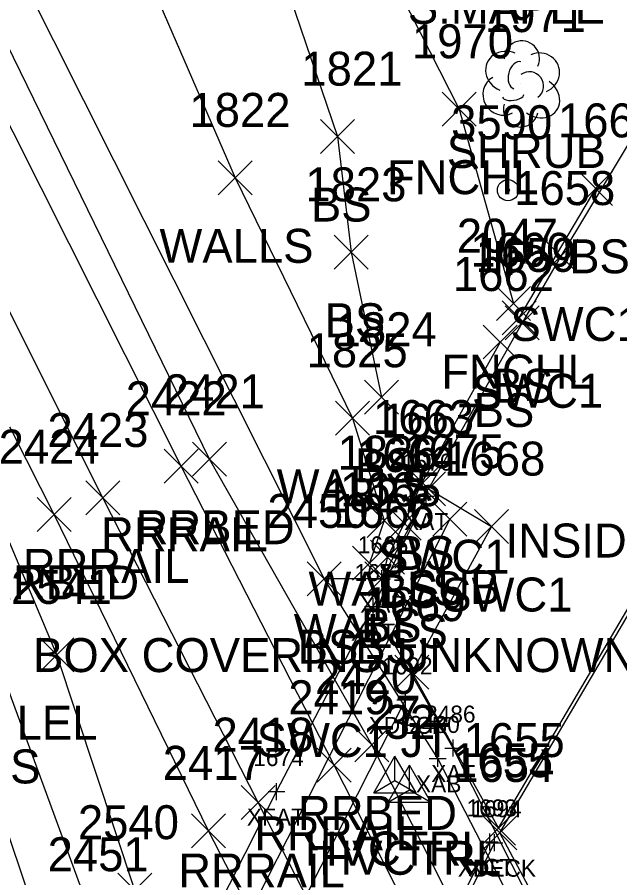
# Model space of a CAD drawing. Extents: x 1462668 to 1465147, y 550359 to 557351.
# Drawn here: x 1464652.7 to 1464688.2, y 552680.5 to 552731.2 of the extents above; entities that cross this region are included whole.
import ezdxf

# ---------------------------------------------------------------- set-up
doc = ezdxf.new("R2010")
doc.units = 0
for name, color, linetype in [('B_A', 7, 'Continuous'), ('B_I', 7, 'Continuous'), ('B_TIC', 7, 'Continuous'), ('BDC', 7, 'Continuous'), ('BELB', 7, 'Continuous'), ('BF', 7, 'Continuous'), ('BSUBM', 7, 'Continuous'), ('C_A', 7, 'Continuous'), ('C_I', 7, 'Continuous'), ('CPSM', 7, 'Continuous'), ('D_C', 7, 'Continuous'), ('L_A', 7, 'Continuous'), ('L_C', 7, 'Continuous'), ('L_I', 7, 'Continuous'), ('L_TIC', 7, 'Continuous'), ('LARO', 7, 'Continuous'), ('LELB', 7, 'Continuous'), ('LFNC', 7, 'Continuous'), ('LSH', 7, 'Continuous'), ('LWS', 7, 'Continuous'), ('M_A', 7, 'Continuous'), ('M_I', 7, 'Continuous'), ('MPIR', 7, 'Continuous'), ('P_I', 7, 'Continuous'), ('P_TIC', 7, 'Continuous'), ('PSP', 7, 'Continuous'), ('R_A', 7, 'Continuous'), ('R_I', 7, 'Continuous'), ('R_TIC', 7, 'Continuous'), ('RC', 7, 'Continuous'), ('RR', 7, 'Continuous'), ('RRB', 7, 'Continuous'), ('RSW', 7, 'Continuous'), ('U_A', 7, 'Continuous'), ('U_C', 7, 'Continuous'), ('U_I', 7, 'Continuous'), ('U_TIC', 7, 'Continuous'), ('UUU', 7, 'Continuous')]:
    doc.layers.add(name, color=color, linetype=linetype)

msp = doc.modelspace()

# ---------------------------------------------------------------- linework, layer by layer
at = {"layer": 'B_TIC'}
for p, q in [((1464676.76, 552702.981), (1464676.836, 552702.981)), ((1464674.159, 552698.116), (1464674.235, 552698.116)), ((1464673.643, 552696.482), (1464673.718, 552696.482)), ((1464675.542, 552690.989), (1464675.618, 552690.989)), ((1464678.359, 552688.151), (1464678.434, 552688.151)), ((1464677.446, 552687.542), (1464677.522, 552687.542)), ((1464667.956, 552685.592), (1464668.032, 552685.592)), ((1464680.517, 552682.631), (1464680.592, 552682.631)), ((1464680.788, 552682.58), (1464680.864, 552682.58))]:
    msp.add_line(p, q, dxfattribs=at)
for points in [[(1464676.757, 552702.481), (1464676.757, 552703.481)], [(1464676.257, 552702.981), (1464677.257, 552702.981)], [(1464674.156, 552697.616), (1464674.156, 552698.616)], [(1464673.656, 552698.116), (1464674.656, 552698.116)], [(1464673.639, 552695.982), (1464673.639, 552696.982)], [(1464673.139, 552696.482), (1464674.139, 552696.482)], [(1464675.539, 552690.489), (1464675.539, 552691.489)], [(1464675.039, 552690.989), (1464676.039, 552690.989)], [(1464678.355, 552687.651), (1464678.355, 552688.651)], [(1464677.443, 552687.042), (1464677.443, 552688.042)], [(1464677.855, 552688.151), (1464678.855, 552688.151)], [(1464676.943, 552687.542), (1464677.943, 552687.542)], [(1464667.953, 552685.092), (1464667.953, 552686.092)], [(1464667.453, 552685.592), (1464668.453, 552685.592)], [(1464680.513, 552682.131), (1464680.513, 552683.131)], [(1464680.785, 552682.08), (1464680.785, 552683.08)], [(1464680.013, 552682.631), (1464681.013, 552682.631)], [(1464680.285, 552682.58), (1464681.285, 552682.58)]]:
    msp.add_lwpolyline(points, dxfattribs=at)
at = {"layer": 'BDC'}
msp.add_lwpolyline([(1464680.513, 552682.631), (1464669.667, 552661.383), (1464666.469, 552656.596)], dxfattribs=at)
at = {"layer": 'BELB'}
for points in [[(1464662.218, 552664.718), (1464666.341, 552672.848), (1464675.539, 552690.989)], [(1464680.785, 552682.58), (1464669.962, 552661.215), (1464666.703, 552656.487)]]:
    msp.add_lwpolyline(points, dxfattribs=at)
at = {"layer": 'BF'}
for points in [[(1464667.953, 552685.592), (1464673.639, 552696.482)], [(1464659.334, 552668.851), (1464662.413, 552674.652), (1464667.953, 552685.592)]]:
    msp.add_lwpolyline(points, dxfattribs=at)
at = {"layer": 'BSUBM'}
for points in [[(1464676.757, 552702.981), (1464673.639, 552696.482)], [(1464674.156, 552698.116), (1464676.757, 552702.981)], [(1464674.156, 552698.116), (1464670.761, 552698.112)], [(1464677.443, 552687.542), (1464670.761, 552698.112)], [(1464678.355, 552688.151), (1464673.639, 552696.482)], [(1464723.043, 552601.401), (1464713.026, 552620.249), (1464708.313, 552629.74), (1464700.555, 552644.714), (1464687.566, 552669.892), (1464678.355, 552688.151)], [(1464722.837, 552599.912), (1464712.418, 552619.848), (1464699.886, 552644.257), (1464686.833, 552669.359), (1464677.443, 552687.542)]]:
    msp.add_lwpolyline(points, dxfattribs=at)
at = {"layer": 'CPSM'}
for p, q in [((1464673.678, 552685.516), (1464674.928, 552687.681)), ((1464676.178, 552685.516), (1464674.928, 552687.681)), ((1464674.928, 552686.237), (1464674.928, 552687.681)), ((1464674.536, 552684.973), (1464675.786, 552687.138)), ((1464677.036, 552684.973), (1464675.786, 552687.138)), ((1464675.786, 552685.694), (1464675.786, 552687.138)), ((1464673.678, 552685.516), (1464674.928, 552686.237)), ((1464674.928, 552686.237), (1464674.928, 552686.237)), ((1464674.928, 552686.237), (1464676.178, 552685.516)), ((1464673.678, 552685.516), (1464676.178, 552685.516)), ((1464674.536, 552684.973), (1464675.786, 552685.694)), ((1464675.786, 552685.694), (1464675.786, 552685.694)), ((1464675.786, 552685.694), (1464677.036, 552684.973)), ((1464674.536, 552684.973), (1464677.036, 552684.973))]:
    msp.add_line(p, q, dxfattribs=at)
at = {"layer": 'L_TIC'}
for points in [[(1464677.707, 552724.755), (1464679.707, 552726.755)], [(1464679.707, 552724.755), (1464677.707, 552726.755)], [(1464670.542, 552723.144), (1464672.542, 552725.144)], [(1464672.542, 552723.144), (1464670.542, 552725.144)], [(1464664.52, 552720.715), (1464666.52, 552722.715)], [(1464666.52, 552720.715), (1464664.52, 552722.715)], [(1464685.745, 552720.098), (1464687.745, 552722.098)], [(1464687.745, 552720.098), (1464685.745, 552722.098)], [(1464671.348, 552716.335), (1464673.348, 552718.335)], [(1464673.348, 552716.335), (1464671.348, 552718.335)], [(1464680.909, 552713.313), (1464682.909, 552715.313)], [(1464682.909, 552713.313), (1464680.909, 552715.313)], [(1464681.243, 552712.482), (1464683.243, 552714.482)], [(1464683.243, 552712.482), (1464681.243, 552714.482)], [(1464680.123, 552711.054), (1464682.123, 552713.054)], [(1464682.123, 552711.054), (1464680.123, 552713.054)], [(1464673.131, 552707.802), (1464675.131, 552709.802)], [(1464675.131, 552707.802), (1464673.131, 552709.802)], [(1464671.421, 552706.566), (1464673.421, 552708.566)], [(1464673.421, 552706.566), (1464671.421, 552708.566)], [(1464675.423, 552702.634), (1464677.423, 552704.634)], [(1464677.423, 552702.634), (1464675.423, 552704.634)], [(1464673.293, 552700.543), (1464675.293, 552702.543)], [(1464675.293, 552700.543), (1464673.293, 552702.543)], [(1464674.475, 552700.398), (1464676.475, 552702.398)], [(1464676.475, 552700.398), (1464674.475, 552702.398)], [(1464672.431, 552698.034), (1464674.431, 552700.034)], [(1464674.431, 552698.034), (1464672.431, 552700.034)], [(1464673.486, 552698.383), (1464675.486, 552700.383)], [(1464675.486, 552698.383), (1464673.486, 552700.383)], [(1464669.761, 552697.112), (1464671.761, 552699.112)], [(1464671.761, 552697.112), (1464669.761, 552699.112)], [(1464673.156, 552697.116), (1464675.156, 552699.116)], [(1464675.156, 552697.116), (1464673.156, 552699.116)], [(1464654.013, 552692.639), (1464656.013, 552694.639)], [(1464656.013, 552692.639), (1464654.013, 552694.639)], [(1464658.607, 552678.788), (1464660.607, 552680.788)], [(1464660.607, 552678.788), (1464658.607, 552680.788)]]:
    msp.add_lwpolyline(points, dxfattribs=at)
at = {"layer": 'LARO'}
msp.add_lwpolyline([(1464658.959, 552674.491), (1464659.607, 552679.788), (1464655.013, 552693.639), (1464649.27, 552707.282)], dxfattribs=at)
at = {"layer": 'LELB'}
for points in [[(1464605.992, 552829.954), (1464617.903, 552805.102), (1464635.924, 552775.462), (1464644.18, 552750.936), (1464670.761, 552698.112)], [(1464591.837, 552823.151), (1464604.584, 552798.4), (1464620.531, 552768.212), (1464633.366, 552738.896), (1464646.04, 552708.211), (1464657.171, 552677.902), (1464659.575, 552669.465), (1464660.96, 552669.665)], [(1464666.872, 552737.886), (1464671.542, 552724.144), (1464672.348, 552717.335), (1464674.131, 552708.802)], [(1464682.243, 552713.482), (1464686.745, 552721.098)], [(1464681.123, 552712.054), (1464676.423, 552703.634), (1464675.475, 552701.398), (1464674.486, 552699.383), (1464674.156, 552698.116)]]:
    msp.add_lwpolyline(points, dxfattribs=at)
at = {"layer": 'LFNC'}
msp.add_lwpolyline([(1464622.755, 552840.374), (1464640.528, 552802.915), (1464653.99, 552774.381), (1464678.707, 552725.755), (1464681.909, 552714.313)], dxfattribs=at)
at = {"layer": 'LSH'}
msp.add_line((1464682.348, 552727.298), (1464682.348, 552727.298), dxfattribs=at)
msp.add_line((1464682.348, 552727.298), (1464682.348, 552727.298), dxfattribs=at)
msp.add_arc((1464682.395, 552728.732), 1.047, 335.5272, 180.9563, dxfattribs=at)
for centre, major_axis, ratio, start_param, end_param in [((1464681.556, 552727.965), (1.21, -0.512), 0.895232, 1.570796, 4.712389), ((1464683.39, 552727.882), (-1.141, -0.483), 0.949671, 1.570796, 4.712389), ((1464682.14, 552727.756), (-0.208, -0.792), 0.645439, 3.141593, 6.283185), ((1464682.848, 552727.131), (-0.5, 0.667), 0.989748, 3.141593, 6.283185), ((1464681.265, 552726.589), (0.584, -1.042), 0.959034, 3.141593, 6.283185), ((1464683.348, 552726.465), (-1.09, 0.792), 0.841452, 1.570796, 4.712389), ((1464681.89, 552726.548), (-0.625, -0.083), 0.423636, 0, 3.141593), ((1464682.348, 552725.798), (0.265, 1.061), 0.942809, 1.570796, 4.712389)]:
    msp.add_ellipse(centre, major_axis=major_axis, ratio=ratio, start_param=start_param, end_param=end_param, dxfattribs=at)
at = {"layer": 'LWS'}
for points in [[(1464627.227, 552807.88), (1464624.579, 552807.197), (1464630.268, 552793.197), (1464640.043, 552768.12), (1464646.829, 552754.919), (1464648.101, 552754.433), (1464659.033, 552736.713), (1464665.52, 552721.715), (1464672.421, 552707.566), (1464674.293, 552701.543), (1464673.431, 552699.034)], [(1464628.323, 552737.747), (1464630.463, 552738.737), (1464636.481, 552723.859), (1464640.409, 552715.693), (1464643.848, 552708.405), (1464644.066, 552707.906), (1464644.246, 552705.998), (1464645.171, 552703.317), (1464649.444, 552691.071), (1464655.056, 552674.447), (1464657.686, 552668.432), (1464659.187, 552668.867)]]:
    msp.add_lwpolyline(points, dxfattribs=at)
at = {"layer": 'MPIR'}
for radius in [0.625, 0.0833]:
    msp.add_circle((1464681.583, 552720.991), radius, dxfattribs=at)
at = {"layer": 'P_TIC'}
for points in [[(1464680.101, 552682.158), (1464682.101, 552684.158)], [(1464682.101, 552682.158), (1464680.101, 552684.158)]]:
    msp.add_lwpolyline(points, dxfattribs=at)
at = {"layer": 'PSP'}
msp.add_lwpolyline([(1464713.42, 552621.664), (1464703.882, 552639.321), (1464698.154, 552650.89), (1464690.708, 552665.219), (1464681.101, 552683.158), (1464703.999, 552722.049), (1464716.476, 552737.914), (1464734.78, 552760.749), (1464735.815, 552761.915), (1464745.244, 552772.268), (1464746.275, 552773.345), (1464761.553, 552790.01), (1464762.974, 552792.101), (1464763.764, 552794.246), (1464784.888, 552812.77), (1464795.307, 552821.347), (1464823.73, 552847.994), (1464827.491, 552852.408)], dxfattribs=at)
at = {"layer": 'R_TIC'}
for points in [[(1464683.688, 552716.115), (1464685.688, 552718.115)], [(1464685.688, 552716.115), (1464683.688, 552718.115)], [(1464681.423, 552712.181), (1464683.423, 552714.181)], [(1464683.423, 552712.181), (1464681.423, 552714.181)], [(1464663.014, 552704.151), (1464665.014, 552706.151)], [(1464665.014, 552704.151), (1464663.014, 552706.151)], [(1464661.335, 552703.74), (1464663.335, 552705.74)], [(1464663.335, 552703.74), (1464661.335, 552705.74)], [(1464675.9, 552702.42), (1464677.9, 552704.42)], [(1464677.9, 552702.42), (1464675.9, 552704.42)], [(1464656.727, 552701.874), (1464658.727, 552703.874)], [(1464658.727, 552701.874), (1464656.727, 552703.874)], [(1464653.855, 552700.899), (1464655.855, 552702.899)], [(1464655.855, 552700.899), (1464653.855, 552702.899)], [(1464679.616, 552700.19), (1464681.616, 552702.19)], [(1464681.616, 552700.19), (1464679.616, 552702.19)], [(1464674.923, 552691.623), (1464676.923, 552693.623)], [(1464676.923, 552691.623), (1464674.923, 552693.623)], [(1464672.574, 552687.335), (1464674.574, 552689.335)], [(1464674.574, 552687.335), (1464672.574, 552689.335)], [(1464670.35, 552686.141), (1464672.35, 552688.141)], [(1464672.35, 552686.141), (1464670.35, 552688.141)], [(1464665.878, 552683.945), (1464667.878, 552685.945)], [(1464667.878, 552683.945), (1464665.878, 552685.945)], [(1464680.027, 552682.437), (1464682.027, 552684.437)], [(1464682.027, 552682.437), (1464680.027, 552684.437)], [(1464662.948, 552682.282), (1464664.948, 552684.282)], [(1464664.948, 552682.282), (1464662.948, 552684.282)]]:
    msp.add_lwpolyline(points, dxfattribs=at)
at = {"layer": 'RC'}
msp.add_lwpolyline([(1464681.027, 552683.437), (1464703.888, 552722.216), (1464716.213, 552738.058), (1464734.65, 552760.884), (1464735.67, 552761.965), (1464745.167, 552772.414), (1464746.115, 552773.418), (1464761.316, 552790.158), (1464762.705, 552792.216), (1464763.558, 552794.277), (1464763.469, 552797.082), (1464762.503, 552800.027), (1464761.265, 552802.911), (1464759.396, 552805.483), (1464759.23, 552805.341)], dxfattribs=at)
at = {"layer": 'RR'}
for points in [[(1464849.389, 552249.534), (1464842.819, 552270.793), (1464835.11, 552294.838), (1464826.262, 552322.52), (1464813.909, 552358.251), (1464808.668, 552373.872), (1464804.992, 552384.746), (1464790.19, 552425.007), (1464777.181, 552458.665), (1464762.364, 552494.605), (1464744.909, 552535.145), (1464735.628, 552555.847), (1464721.293, 552586.6), (1464702.021, 552626.346), (1464686.842, 552656.687), (1464671.35, 552687.141), (1464662.335, 552704.74), (1464642.534, 552744.081), (1464629.159, 552771.135), (1464613.477, 552803.16), (1464601.343, 552828.316)], [(1464844.813, 552247.755), (1464838.177, 552269.149), (1464830.386, 552293.617), (1464821.392, 552321.548), (1464809.517, 552356.645), (1464804.149, 552372.473), (1464800.295, 552383.078), (1464785.596, 552423.206), (1464772.719, 552456.472), (1464757.811, 552492.705), (1464740.233, 552533.386), (1464731.218, 552553.662), (1464716.736, 552584.611), (1464697.665, 552624.112), (1464682.453, 552654.497), (1464666.878, 552684.945), (1464657.727, 552702.874), (1464638.134, 552741.98), (1464624.708, 552768.998), (1464609.228, 552800.971), (1464596.703, 552826.136)]]:
    msp.add_lwpolyline(points, dxfattribs=at)
at = {"layer": 'RRB'}
for points in [[(1464851.042, 552250.445), (1464845.147, 552271.635), (1464837.544, 552295.462), (1464828.768, 552323.575), (1464816.78, 552359.11), (1464810.928, 552374.769), (1464807.843, 552386.028), (1464792.774, 552426.038), (1464778.944, 552461.754), (1464771.168, 552477.614), (1464764.619, 552495.611), (1464747.04, 552536.302), (1464737.618, 552557.165), (1464723.44, 552587.94), (1464704.535, 552627.922), (1464689.191, 552657.618), (1464673.574, 552688.335), (1464664.014, 552705.151), (1464644.495, 552745.11), (1464631.556, 552772.375), (1464615.641, 552804.178), (1464603.908, 552829.416)], [(1464842.442, 552246.931), (1464836.486, 552268.553), (1464828.066, 552292.901), (1464819.091, 552320.895), (1464807.286, 552355.87), (1464801.457, 552371.532), (1464797.599, 552381.724), (1464783.012, 552422.471), (1464769.406, 552454.584), (1464755.315, 552491.81), (1464738.611, 552532.376), (1464729.391, 552552.755), (1464715, 552583.837), (1464695.071, 552622.976), (1464679.554, 552652.995), (1464663.948, 552683.282), (1464654.855, 552701.899), (1464635.344, 552740.456), (1464622.383, 552767.72), (1464607.066, 552799.752), (1464594.744, 552825)]]:
    msp.add_lwpolyline(points, dxfattribs=at)
at = {"layer": 'RSW'}
for points in [[(1464703.976, 552749.325), (1464692.548, 552730.159), (1464684.688, 552717.115), (1464682.423, 552713.181), (1464676.9, 552703.42), (1464680.616, 552701.19), (1464675.923, 552692.623)], [(1464675.923, 552692.623), (1464681.027, 552683.437)]]:
    msp.add_lwpolyline(points, dxfattribs=at)
at = {"layer": 'U_TIC'}
for points in [[(1464677.157, 552700.624), (1464679.157, 552702.624)], [(1464679.157, 552700.624), (1464677.157, 552702.624)]]:
    msp.add_lwpolyline(points, dxfattribs=at)
at = {"layer": 'UUU'}
msp.add_lwpolyline([(1464678.157, 552701.624), (1464658.996, 552663.944), (1464742.881, 552478.871)], dxfattribs=at)

# ---------------------------------------------------------------- texts
at = {"layer": 'B_A'}
for s, p in [('XAT', (1464675.462, 552700.981)), ('XAB', (1464672.876, 552696.116)), ('XAT', (1464672.344, 552694.482)), ('XDECK', (1464673.381, 552688.989)), ('XAT', (1464677.06, 552686.151)), ('XAB', (1464676.163, 552685.542)), ('XFAT', (1464666.209, 552683.592)), ('XDECK', (1464678.627, 552680.58)), ('XCT', (1464679.234, 552680.631))]:
    msp.add_text(s, height=1, dxfattribs=at).set_placement(p)
at = {"layer": 'B_I'}
for s, p in [('1670', (1464675.343, 552704.481)), ('1666', (1464672.735, 552699.616)), ('1671', (1464672.553, 552697.982)), ('1692', (1464674.169, 552692.489)), ('2486', (1464676.698, 552689.651)), ('2480', (1464675.77, 552689.042)), ('1674', (1464666.583, 552687.092)), ('1693', (1464679.143, 552684.131)), ('1694', (1464679.415, 552684.08))]:
    msp.add_text(s, height=1, dxfattribs=at).set_placement(p)
at = {"layer": 'C_A'}
for p in [(1464669.621, 552681.237), (1464670.479, 552680.694)]:
    msp.add_text('HVCTRL', height=2, dxfattribs=at).set_placement(p)
at = {"layer": 'C_I'}
for s, p in [('27', (1464673.464, 552689.237)), ('32', (1464674.321, 552688.694))]:
    msp.add_text(s, height=2, dxfattribs=at).set_placement(p)
at = {"layer": 'D_C'}
msp.add_text('INSIDE IS FALLING IN', height=2, dxfattribs=at).set_placement((1464681.441, 552699.367))
at = {"layer": 'L_A'}
for s, p in [('SHRUB', (1464677.978, 552722.298)), ('FNCHL', (1464674.455, 552720.755)), ('BS', (1464669.982, 552719.144)), ('WALLS', (1464661.063, 552716.715)), ('BS', (1464685.186, 552716.098)), ('BS', (1464670.789, 552712.335)), ('FNCHL', (1464677.657, 552709.313)), ('BS', (1464680.684, 552708.482)), ('BS', (1464679.564, 552707.054)), ('BS', (1464672.572, 552703.802)), ('WALLS', (1464667.964, 552702.566)), ('BS', (1464674.864, 552698.634)), ('WALLS', (1464669.836, 552696.543)), ('BS', (1464673.916, 552696.398)), ('WALLS', (1464668.974, 552694.034)), ('BS', (1464672.927, 552694.383)), ('BS', (1464669.202, 552693.112)), ('BS', (1464672.597, 552693.116)), ('LEL', (1464652.651, 552688.639)), ('WALLS', (1464644.987, 552686.071))]:
    msp.add_text(s, height=2, dxfattribs=at).set_placement(p)
at = {"layer": 'L_C'}
msp.add_text('S.MAPLE', height=2, dxfattribs=at).set_placement((1464675.691, 552730.783))
at = {"layer": 'L_I'}
for s, p in [('1971', (1464680.222, 552730.298)), ('1970', (1464675.928, 552728.755)), ('1821', (1464669.416, 552727.144)), ('1822', (1464662.827, 552724.715)), ('1661', (1464684.525, 552724.098)), ('1823', (1464669.655, 552720.335)), ('2047', (1464678.57, 552717.313)), ('1660', (1464679.369, 552716.482)), ('1662', (1464678.336, 552715.054)), ('1824', (1464671.438, 552711.802)), ('1825', (1464669.728, 552710.566)), ('1663', (1464673.635, 552706.634)), ('1826', (1464671.545, 552704.543)), ('1664', (1464672.688, 552704.398)), ('1665', (1464671.699, 552702.383)), ('1827', (1464670.738, 552702.034)), ('2450', (1464667.415, 552701.112)), ('1666', (1464671.313, 552701.116)), ('2541', (1464652.321, 552696.639)), ('2540', (1464656.261, 552682.788)), ('2451', (1464654.478, 552680.902))]:
    msp.add_text(s, height=2, dxfattribs=at).set_placement(p)
at = {"layer": 'M_A'}
msp.add_text('IP', height=2, dxfattribs=at).set_placement((1464680.631, 552715.991))
at = {"layer": 'M_I'}
msp.add_text('3590', height=2, dxfattribs=at).set_placement((1464678.237, 552723.991))
at = {"layer": 'P_I'}
msp.add_text('1654', height=2, dxfattribs=at).set_placement((1464678.361, 552686.158))
at = {"layer": 'R_A'}
for s, p in [('SWC1', (1464681.728, 552712.115)), ('SWC1', (1464679.463, 552708.181)), ('RRBED', (1464659.66, 552700.151)), ('RRRAIL', (1464657.626, 552699.74)), ('SWC1', (1464673.94, 552698.42)), ('RRRAIL', (1464653.018, 552697.874)), ('RRBED', (1464650.501, 552696.899)), ('SWC1', (1464677.655, 552696.19)), ('SWC1 JT 1655', (1464666.789, 552687.623)), ('RRBED', (1464669.219, 552683.335)), ('RRRAIL', (1464666.642, 552682.141)), ('RRRAIL', (1464662.169, 552679.945))]:
    msp.add_text(s, height=2, dxfattribs=at).set_placement(p)
at = {"layer": 'R_I'}
for s, p in [('1658', (1464681.948, 552720.115)), ('1659', (1464679.675, 552716.181)), ('2421', (1464661.321, 552708.151)), ('2422', (1464659.075, 552707.74)), ('1667', (1464674.113, 552706.42)), ('2423', (1464654.467, 552705.874)), ('2424', (1464651.595, 552704.899)), ('1668', (1464677.828, 552704.19)), ('1669', (1464673.128, 552695.623)), ('2420', (1464670.227, 552691.335)), ('2419', (1464668.65, 552690.141)), ('2418', (1464664.185, 552687.945)), ('1655', (1464678.287, 552686.437)), ('2417', (1464661.255, 552686.282))]:
    msp.add_text(s, height=2, dxfattribs=at).set_placement(p)
at = {"layer": 'U_A'}
msp.add_text('SUB', height=2, dxfattribs=at).set_placement((1464675.63, 552696.624))
at = {"layer": 'U_C'}
msp.add_text('BOX COVERING UNKNOWN UTILITY', height=2, dxfattribs=at).set_placement((1464653.622, 552692.624))
at = {"layer": 'U_I'}
msp.add_text('1675', height=2, dxfattribs=at).set_placement((1464675.417, 552704.624))

doc.saveas('drawing.dxf')
